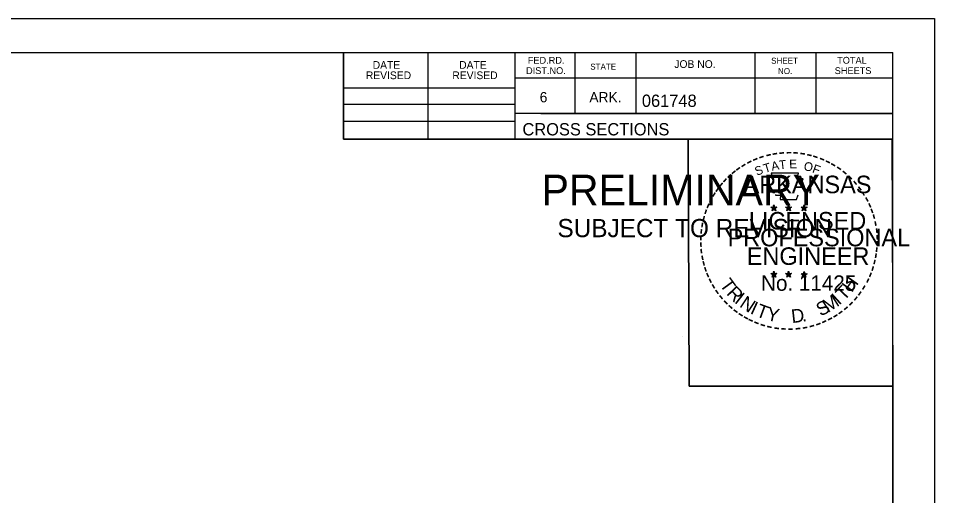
# Model space of a CAD drawing. Extents: x 961436 to 1372525, y 380079 to 2027791.
# Drawn here: x 1370692.3 to 1370796.7, y 380268 to 380322.4 of the extents above; entities that cross this region are included whole.
import ezdxf

# ---------------------------------------------------------------- set-up
doc = ezdxf.new("R2010")
doc.units = 0
doc.layers.add('R_No Plot', color=7, linetype='Continuous')

msp = doc.modelspace()

# ---------------------------------------------------------------- linework, layer by layer
at = {"layer": 'R_No Plot'}
for p, q in [((1370463.41, 380322.41), (1370796.74, 380322.41)), ((1370475.81, 380318.52), (1370791.99, 380318.52)), ((1370729.35, 380308.64), (1370729.35, 380318.52)), ((1370739.03, 380308.64), (1370739.03, 380318.52)), ((1370748.89, 380318.52), (1370748.89, 380308.64)), ((1370755.73, 380318.52), (1370755.73, 380311.58)), ((1370762.67, 380318.52), (1370762.67, 380311.58)), ((1370776.25, 380318.52), (1370776.25, 380311.58)), ((1370783.19, 380318.52), (1370783.19, 380311.58)), ((1370791.99, 380113.06), (1370791.99, 380318.52)), ((1370791.99, 380315.6), (1370791.99, 380315.6)), ((1370791.99, 380315.58), (1370748.89, 380315.58)), ((1370729.35, 380314.5), (1370748.89, 380314.5)), ((1370729.35, 380312.64), (1370748.89, 380312.64)), ((1370791.99, 380311.58), (1370748.89, 380311.58)), ((1370751.85, 380311.58), (1370791.99, 380311.58)), ((1370729.35, 380310.7), (1370748.89, 380310.7)), ((1370791.99, 380308.64), (1370729.35, 380308.64)), ((1370778.43, 380301.15), (1370778.39, 380300.9)), ((1370778.43, 380300.78), (1370778.43, 380301.15)), ((1370778.43, 380301.15), (1370778.48, 380300.9)), ((1370780.1, 380301.15), (1370780.06, 380300.9)), ((1370780.1, 380300.78), (1370780.1, 380301.15)), ((1370780.1, 380301.15), (1370780.15, 380300.9)), ((1370781.86, 380301.14), (1370781.82, 380300.88)), ((1370781.86, 380300.77), (1370781.86, 380301.14)), ((1370781.86, 380301.14), (1370781.91, 380300.89)), ((1370778.08, 380300.89), (1370778.43, 380300.78)), ((1370778.08, 380300.89), (1370778.33, 380300.85)), ((1370778.08, 380300.89), (1370778.31, 380300.77)), ((1370778.21, 380300.49), (1370778.43, 380300.78)), ((1370778.21, 380300.49), (1370778.34, 380300.73)), ((1370778.21, 380300.49), (1370778.42, 380300.7)), ((1370778.64, 380300.49), (1370778.42, 380300.7)), ((1370778.77, 380300.89), (1370778.43, 380300.78)), ((1370778.64, 380300.49), (1370778.43, 380300.78)), ((1370778.77, 380300.89), (1370778.49, 380300.85)), ((1370778.64, 380300.49), (1370778.5, 380300.78)), ((1370778.77, 380300.89), (1370778.57, 380300.79)), ((1370779.75, 380300.89), (1370780.1, 380300.78)), ((1370779.75, 380300.89), (1370780, 380300.85)), ((1370779.75, 380300.89), (1370779.98, 380300.77)), ((1370779.88, 380300.49), (1370780.1, 380300.78)), ((1370779.88, 380300.49), (1370780.01, 380300.73)), ((1370779.88, 380300.49), (1370780.09, 380300.7)), ((1370780.31, 380300.49), (1370780.09, 380300.7)), ((1370780.44, 380300.89), (1370780.1, 380300.78)), ((1370780.31, 380300.49), (1370780.1, 380300.78)), ((1370780.44, 380300.89), (1370780.16, 380300.85)), ((1370780.31, 380300.49), (1370780.17, 380300.78)), ((1370780.44, 380300.89), (1370780.24, 380300.79)), ((1370781.51, 380300.88), (1370781.86, 380300.77)), ((1370781.51, 380300.88), (1370781.76, 380300.84)), ((1370781.51, 380300.88), (1370781.75, 380300.76)), ((1370781.64, 380300.47), (1370781.86, 380300.77)), ((1370781.64, 380300.47), (1370781.77, 380300.72)), ((1370781.64, 380300.47), (1370781.86, 380300.69)), ((1370782.21, 380300.88), (1370781.86, 380300.77)), ((1370782.07, 380300.47), (1370781.86, 380300.77)), ((1370782.07, 380300.47), (1370781.86, 380300.69)), ((1370782.21, 380300.88), (1370781.92, 380300.83)), ((1370782.07, 380300.47), (1370781.94, 380300.77)), ((1370782.21, 380300.88), (1370782, 380300.78)), ((1370778.07, 380293.32), (1370778.42, 380293.21)), ((1370778.07, 380293.32), (1370778.33, 380293.28)), ((1370778.07, 380293.32), (1370778.31, 380293.2)), ((1370778.21, 380292.91), (1370778.42, 380293.21)), ((1370778.21, 380292.91), (1370778.33, 380293.16)), ((1370778.21, 380292.91), (1370778.42, 380293.13)), ((1370778.42, 380293.58), (1370778.38, 380293.32)), ((1370778.42, 380293.21), (1370778.42, 380293.58)), ((1370778.42, 380293.58), (1370778.47, 380293.33)), ((1370778.77, 380293.32), (1370778.42, 380293.21)), ((1370778.64, 380292.91), (1370778.42, 380293.21)), ((1370778.64, 380292.91), (1370778.42, 380293.13)), ((1370778.77, 380293.32), (1370778.48, 380293.27)), ((1370778.64, 380292.91), (1370778.5, 380293.2)), ((1370778.77, 380293.32), (1370778.57, 380293.22)), ((1370779.74, 380293.32), (1370780.09, 380293.21)), ((1370779.74, 380293.32), (1370780, 380293.28)), ((1370779.74, 380293.32), (1370779.98, 380293.2)), ((1370779.88, 380292.91), (1370780.09, 380293.21)), ((1370779.88, 380292.91), (1370780, 380293.16)), ((1370779.88, 380292.91), (1370780.09, 380293.13)), ((1370780.09, 380293.58), (1370780.05, 380293.32)), ((1370780.09, 380293.21), (1370780.09, 380293.58)), ((1370780.09, 380293.58), (1370780.14, 380293.33)), ((1370780.44, 380293.32), (1370780.09, 380293.21)), ((1370780.3, 380292.91), (1370780.09, 380293.21)), ((1370780.3, 380292.91), (1370780.09, 380293.13)), ((1370780.44, 380293.32), (1370780.15, 380293.27)), ((1370780.3, 380292.91), (1370780.17, 380293.2)), ((1370780.44, 380293.32), (1370780.23, 380293.22)), ((1370781.51, 380293.31), (1370781.86, 380293.2)), ((1370781.51, 380293.31), (1370781.76, 380293.27)), ((1370781.51, 380293.31), (1370781.75, 380293.19)), ((1370781.64, 380292.9), (1370781.86, 380293.2)), ((1370781.64, 380292.9), (1370781.77, 380293.15)), ((1370781.64, 380292.9), (1370781.86, 380293.12)), ((1370781.86, 380293.57), (1370781.82, 380293.31)), ((1370781.86, 380293.2), (1370781.86, 380293.57)), ((1370781.86, 380293.57), (1370781.91, 380293.32)), ((1370782.21, 380293.31), (1370781.86, 380293.2)), ((1370782.07, 380292.9), (1370781.86, 380293.2)), ((1370782.07, 380292.9), (1370781.86, 380293.12)), ((1370782.21, 380293.31), (1370781.92, 380293.26)), ((1370782.07, 380292.9), (1370781.93, 380293.19)), ((1370782.21, 380293.31), (1370782, 380293.21)), ((1370768.03, 380286.18), (1370768.03, 380286.18))]:
    msp.add_line(p, q, dxfattribs=at)
for points in [[(1370463.4, 380322.41), (1370796.74, 380322.41), (1370796.74, 380109.08), (1370463.4, 380109.08)], [(1370709.73, 380318.52), (1370729.35, 380318.52), (1370729.35, 380308.64), (1370745.46, 380308.64), (1370768.66, 380308.64), (1370768.78, 380280.48), (1370791.99, 380280.48), (1370791.99, 380113.06), (1370475.81, 380113.06), (1370475.81, 380318.52)], [(1370768.66, 380308.64), (1370791.87, 380308.64), (1370791.99, 380280.48), (1370768.78, 380280.48)]]:
    msp.add_lwpolyline(points, close=True, dxfattribs=at)
for points in [[(1370778.12, 380304.77), (1370778.39, 380303.95)], [(1370781.63, 380303.85), (1370781.77, 380304.13), (1370781.09, 380304.11), (1370781.23, 380304.77), (1370778.12, 380304.77)], [(1370778.61, 380302.35), (1370778.61, 380302.26), (1370779.17, 380302.24), (1370779.12, 380301.77), (1370780.99, 380301.77), (1370781.19, 380302.31)], [(1370778.43, 380301.15), (1370778.64, 380300.49), (1370778.08, 380300.89), (1370778.77, 380300.89), (1370778.21, 380300.49), (1370778.43, 380301.15)], [(1370780.1, 380301.15), (1370780.31, 380300.49), (1370779.75, 380300.89), (1370780.44, 380300.89), (1370779.88, 380300.49), (1370780.1, 380301.15)], [(1370781.86, 380301.14), (1370782.07, 380300.47), (1370781.51, 380300.88), (1370782.21, 380300.88), (1370781.64, 380300.47), (1370781.86, 380301.14)], [(1370778.42, 380293.58), (1370778.64, 380292.91), (1370778.07, 380293.32), (1370778.77, 380293.32), (1370778.21, 380292.91), (1370778.42, 380293.58)], [(1370780.09, 380293.58), (1370780.3, 380292.91), (1370779.74, 380293.32), (1370780.44, 380293.32), (1370779.88, 380292.91), (1370780.09, 380293.58)], [(1370781.86, 380293.57), (1370782.07, 380292.9), (1370781.51, 380293.31), (1370782.21, 380293.31), (1370781.64, 380292.9), (1370781.86, 380293.57)]]:
    msp.add_lwpolyline(points, dxfattribs=at)
for centre, radius in [((1370778.43, 380300.78), 0.172), ((1370778.43, 380300.78), 0.145), ((1370778.43, 380300.78), 0.116), ((1370778.43, 380300.78), 0.0991), ((1370778.43, 380300.78), 0.0747), ((1370778.43, 380300.78), 0.0495), ((1370778.43, 380300.78), 0.0296), ((1370780.1, 380300.78), 0.172), ((1370780.1, 380300.78), 0.145), ((1370780.1, 380300.78), 0.116), ((1370780.1, 380300.78), 0.0991), ((1370780.1, 380300.78), 0.0747), ((1370780.1, 380300.78), 0.0495), ((1370780.1, 380300.78), 0.0296), ((1370781.86, 380300.77), 0.172), ((1370781.86, 380300.77), 0.145), ((1370781.86, 380300.77), 0.116), ((1370781.86, 380300.77), 0.0991), ((1370781.86, 380300.77), 0.0747), ((1370781.86, 380300.77), 0.0495), ((1370781.86, 380300.77), 0.0296), ((1370778.42, 380293.21), 0.172), ((1370778.42, 380293.21), 0.145), ((1370778.42, 380293.21), 0.116), ((1370778.42, 380293.21), 0.0991), ((1370778.42, 380293.21), 0.0747), ((1370778.42, 380293.21), 0.0495), ((1370778.42, 380293.21), 0.0296), ((1370780.09, 380293.21), 0.172), ((1370780.09, 380293.21), 0.145), ((1370780.09, 380293.21), 0.116), ((1370780.09, 380293.21), 0.0991), ((1370780.09, 380293.21), 0.0747), ((1370780.09, 380293.21), 0.0495), ((1370780.09, 380293.21), 0.0296), ((1370781.86, 380293.2), 0.172), ((1370781.86, 380293.2), 0.145), ((1370781.86, 380293.2), 0.116), ((1370781.86, 380293.2), 0.0991), ((1370781.86, 380293.2), 0.0747), ((1370781.86, 380293.2), 0.0495), ((1370781.86, 380293.2), 0.0296)]:
    msp.add_circle(centre, radius, dxfattribs=at)

# ---------------------------------------------------------------- texts
for s, height, rotation, p in [('FED.RD.', 0.782, 360, (1370750.37, 380317.24)), ('SHEET', 0.684, 360, (1370778.11, 380317.24)), ('TOTAL', 0.782, 360, (1370785.63, 380317.24)), ('DATE', 0.879, 360, (1370732.69, 380316.66)), ('DATE', 0.879, 360, (1370742.55, 380316.66)), ('DIST.NO.', 0.782, 360, (1370750.17, 380316.06)), ('STATE', 0.684, 360, (1370757.49, 380316.56)), ('JOB NO.', 0.879, 360, (1370767.07, 380316.76)), ('NO.', 0.684, 360, (1370778.89, 380316.06)), ('SHEETS', 0.782, 360, (1370785.35, 380316.06)), ('REVISED', 0.879, 360, (1370731.91, 380315.48)), ('REVISED', 0.879, 360, (1370741.77, 380315.48)), ('6', 1.17, 360, (1370751.73, 380312.84)), ('ARK.', 1.172, 360, (1370757.39, 380312.84)), ('061748', 1.4, 360, (1370763.37, 380312.32)), ('CROSS SECTIONS', 1.4, 360, (1370749.76, 380309.07)), ('-', 1.6, 28.7918, (1370775.6, 380305.31)), ('-', 1.6, 24.3072, (1370776.23, 380305.63)), ('-', 1.6, 19.1761, (1370776.87, 380305.9)), ('-', 1.6, 13.6301, (1370777.62, 380306.14)), ('-', 1.6, 10.2193, (1370778.29, 380306.3)), ('T', 1, 6.0228, (1370779.06, 380305.2)), ('-', 1.6, 5.8968, (1370779.02, 380306.41)), ('-', 1.6, 0.1862, (1370779.79, 380306.48)), ('E', 1, 0.8323, (1370780.17, 380305.31)), ('-', 1.6, 357.743, (1370780.52, 380306.47)), ('-', 1.6, 352.1617, (1370781.26, 380306.42)), ('-', 1.6, 347.2049, (1370781.98, 380306.3)), ('-', 1.6, 342.3362, (1370782.62, 380306.15)), ('-', 1.6, 337.8551, (1370783.35, 380305.92)), ('-', 1.6, 334.1211, (1370783.98, 380305.65)), ('-', 1.6, 36.2317, (1370774.42, 380304.55)), ('-', 1.6, 34.0636, (1370775, 380304.94)), ('S', 1, 21.594, (1370776.47, 380304.45)), ('T', 1, 16.4036, (1370777.39, 380304.78)), ('A', 1, 11.2132, (1370778.21, 380305.03)), ('O', 1, 350.4515, (1370781.77, 380305.1)), ('F', 1, 340.0707, (1370782.72, 380304.87)), ('-', 1.6, 329.6409, (1370784.56, 380305.37)), ('-', 1.6, 325.8627, (1370785.2, 380305.01)), ('PRELIMINARY', 3.5, 360, (1370751.94, 380301.1)), ('-', 1.6, 48.423, (1370773.07, 380303.28)), ('-', 1.6, 42.9622, (1370773.51, 380303.75)), ('-', 1.6, 38.9507, (1370773.95, 380304.17)), ('ARKANSAS', 2, 360, (1370774.97, 380302.48)), ('-', 1.6, 320.5297, (1370785.81, 380304.58)), ('-', 1.6, 315.5786, (1370786.41, 380304.09)), ('-', 1.6, 54.2325, (1370772.25, 380302.22)), ('-', 1.6, 50.6142, (1370772.66, 380302.79)), ('-', 1.6, 309.8797, (1370786.98, 380303.54)), ('-', 1.6, 306.6522, (1370787.51, 380302.94)), ('DWB', 0.01, 360, (1370752.69, 380302.95)), ('-', 1.6, 58.0706, (1370771.93, 380301.7)), ('-', 1.4, 303.6753, (1370787.99, 380302.37)), ('-', 1.6, 299.6684, (1370788.31, 380301.77)), ('-', 1.6, 67.7743, (1370771.35, 380300.47)), ('-', 1.6, 62.8713, (1370771.61, 380301.08)), ('-', 1.6, 294.6628, (1370788.64, 380301.16)), ('-', 1.6, 72.3945, (1370771.13, 380299.84)), ('LICENSED', 2, 360, (1370775.57, 380298.34)), ('DWB', 0.01, 360, (1370778.41, 380300.78)), ('DWB', 0.01, 360, (1370780.08, 380300.78)), ('DWB', 0.01, 360, (1370781.85, 380300.77)), ('-', 1.6, 290.5728, (1370788.89, 380300.58)), ('-', 1.6, 285.1233, (1370789.13, 380300)), ('SUBJECT TO REVISION', 2.0751, 360, (1370753.75, 380297.47)), ('-', 1.6, 81.2013, (1370770.81, 380298.41)), ('-', 1.6, 75.461, (1370770.94, 380299.13)), ('-', 1.6, 280.5493, (1370789.33, 380299.26)), ('-', 1.6, 85.1863, (1370770.73, 380297.72)), ('PROFESSIONAL', 2, 360, (1370773.14, 380296.43)), ('-', 1.6, 276.5962, (1370789.49, 380298.49)), ('-', 1.6, 94.1959, (1370770.74, 380296.3)), ('-', 1.6, 89.0622, (1370770.7, 380297.02)), ('-', 1.6, 274.3301, (1370789.55, 380297.77)), ('-', 1.6, 269.9407, (1370789.58, 380297.13)), ('-', 1.6, 98.9479, (1370770.81, 380295.63)), ('ENGINEER', 2, 360, (1370775.33, 380294.31)), ('-', 1.6, 263.5172, (1370789.56, 380296.47)), ('-', 1.6, 101.7149, (1370770.95, 380294.9)), ('-', 1.6, 105.4578, (1370771.11, 380294.3)), ('-', 1.6, 255.7626, (1370789.38, 380295.14)), ('-', 1.6, 260.9953, (1370789.49, 380295.81)), ('-', 1.6, 109.0874, (1370771.32, 380293.67)), ('-', 1.6, 252.8681, (1370789.2, 380294.42)), ('-', 1.6, 114.0643, (1370771.58, 380293.07)), ('-', 1.6, 115.7289, (1370771.88, 380292.46)), ('T', 1.54, 306.0406, (1370772.18, 380292.05)), ('No. 11425', 1.757, 360, (1370776.96, 380291.36)), ('DWB', 0.01, 360, (1370778.41, 380293.21)), ('DWB', 0.01, 360, (1370780.08, 380293.21)), ('DWB', 0.01, 360, (1370781.85, 380293.2)), ('H', 1.54, 54.6088, (1370787.3, 380291.08)), ('-', 1.6, 244.6197, (1370788.72, 380293.11)), ('-', 1.6, 247.8887, (1370788.98, 380293.74)), ('-', 1.6, 120.4471, (1370772.24, 380291.87)), ('R', 1.54, 314.005, (1370772.94, 380291)), ('T', 1.54, 46.6444, (1370786.41, 380290.14)), ('-', 1.6, 239.0712, (1370788.32, 380292.36)), ('-', 1.6, 125.8934, (1370772.64, 380291.31)), ('-', 1.6, 130.7181, (1370773.1, 380290.76)), ('I', 1.54, 321.9694, (1370773.84, 380290.07)), ('N', 1.54, 326.5002, (1370774.41, 380289.6)), ('M', 1.54, 32.6563, (1370784.57, 380288.82)), ('I', 1.54, 42.1136, (1370785.85, 380289.66)), ('-', 1.6, 231.2538, (1370787.49, 380291.14)), ('-', 1.6, 233.8452, (1370787.92, 380291.71)), ('-', 1.6, 134.2238, (1370773.62, 380290.21)), ('-', 1.6, 138.9338, (1370774.15, 380289.75)), ('I', 1.54, 335.3603, (1370775.62, 380288.81)), ('T', 1.54, 339.8912, (1370776.28, 380288.48)), ('Y', 1.54, 347.8556, (1370777.5, 380288.04)), ('S', 1.54, 26.9312, (1370783.73, 380288.41)), ('-', 1.6, 221.0851, (1370786.49, 380290.07)), ('-', 1.6, 225.7653, (1370787.01, 380290.58)), ('-', 1.6, 144.6463, (1370774.7, 380289.34)), ('-', 1.6, 148.0898, (1370775.26, 380288.97)), ('-', 1.6, 151.5704, (1370775.84, 380288.65)), ('D', 1.54, 6.3969, (1370780.48, 380287.68)), ('-', 1.6, 212.2491, (1370785.41, 380289.21)), ('-', 1.6, 215.7363, (1370785.94, 380289.6)), ('-', 1.6, 154.6002, (1370776.36, 380288.4)), ('-', 1.6, 158.5612, (1370776.99, 380288.15)), ('-', 1.6, 162.7983, (1370777.68, 380287.93)), ('-', 1.6, 167.5555, (1370778.39, 380287.77)), ('.', 1.54, 13.7642, (1370781.67, 380287.81)), ('-', 1.6, 195.4743, (1370782.93, 380288.03)), ('-', 1.6, 200.7184, (1370783.61, 380288.27)), ('-', 1.6, 204.2516, (1370784.22, 380288.55)), ('-', 1.6, 207.3568, (1370784.85, 380288.87)), ('-', 1.6, 173.1155, (1370779.16, 380287.66)), ('-', 1.6, 176.5183, (1370779.91, 380287.61)), ('-', 1.6, 181.5918, (1370780.65, 380287.62)), ('-', 1.6, 185.8167, (1370781.46, 380287.7)), ('-', 1.6, 191.2858, (1370782.2, 380287.83))]:
    msp.add_text(s, height=height, rotation=rotation, dxfattribs=at).set_placement(p)

doc.saveas('drawing.dxf')
